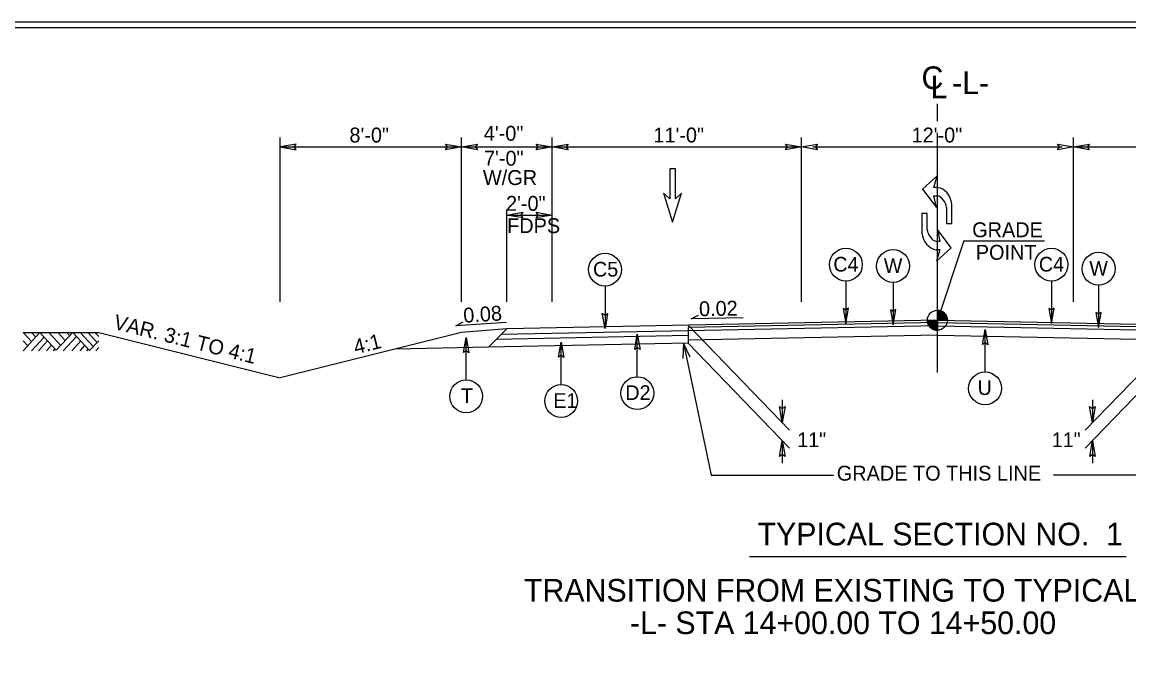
# Model space of a CAD drawing. Extents: x 1901718 to 1902220, y 193828 to 194187.
# Drawn here: x 1902010.31 to 1902059.14, y 194017.77 to 194045.77 of the extents above; entities that cross this region are included whole.
import ezdxf

# ---------------------------------------------------------------- set-up
doc = ezdxf.new("R2010")
doc.units = 0
for name, color, linetype in [('MARK BIKE LEFT ARROW CELL', 7, 'Continuous'), ('Old_Level_1', 7, 'Continuous'), ('Old_Level_11', 7, 'Continuous'), ('Old_Level_2', 7, 'Continuous'), ('Old_Level_20', 7, 'Continuous'), ('Old_Level_3', 7, 'Continuous'), ('Prop Dimension', 7, 'Continuous'), ('Prop Dimension Text', 7, 'Continuous'), ('Sheet Border Standard 30in CELL', 7, 'Continuous'), ('Sheet Plot Border Inside CELL', 7, 'Continuous'), ('Typical Terminator CELL', 7, 'Continuous')]:
    doc.layers.add(name, color=color, linetype=linetype)

# ---------------------------------------------------------------- blocks, each defined once
blk = doc.blocks.new('TERMINATOR')
at = {"layer": 'Typical Terminator CELL'}
blk.add_lwpolyline([(-0.469, 0.081), (0, 0), (-0.471, -0.083), (-0.411, 0)], close=True, dxfattribs=at)

msp = doc.modelspace()

# ---------------------------------------------------------------- linework, layer by layer
at = {"layer": 'MARK BIKE LEFT ARROW CELL'}
for p, q in [((1902050.682, 194038.984), (1902050.031, 194038.399)), ((1902050.682, 194038.984), (1902050.031, 194038.399)), ((1902050.531, 194038.476), (1902050.682, 194038.984)), ((1902050.531, 194038.476), (1902050.682, 194038.984)), ((1902050.031, 194038.399), (1902050.647, 194037.591)), ((1902050.031, 194038.399), (1902050.647, 194037.591)), ((1902050.705, 194038.476), (1902050.531, 194038.476)), ((1902050.705, 194038.476), (1902050.531, 194038.476)), ((1902050.531, 194038.11), (1902050.685, 194038.111)), ((1902050.531, 194038.11), (1902050.685, 194038.111)), ((1902050.647, 194037.591), (1902050.531, 194038.11)), ((1902050.647, 194037.591), (1902050.531, 194038.11)), ((1902051.096, 194037.591), (1902051.096, 194036.885)), ((1902051.096, 194037.591), (1902051.096, 194036.885)), ((1902051.327, 194036.885), (1902051.327, 194037.745)), ((1902051.327, 194036.885), (1902051.327, 194037.745)), ((1902050.241, 194037.323), (1902050.01, 194037.323)), ((1902050.01, 194037.323), (1902050.01, 194036.463)), ((1902050.241, 194037.323), (1902050.01, 194037.323)), ((1902050.01, 194037.323), (1902050.01, 194036.463)), ((1902050.241, 194036.617), (1902050.241, 194037.323)), ((1902050.241, 194036.617), (1902050.241, 194037.323)), ((1902051.096, 194036.885), (1902051.327, 194036.885)), ((1902051.096, 194036.885), (1902051.327, 194036.885)), ((1902051.306, 194035.808), (1902050.69, 194036.617)), ((1902050.69, 194036.617), (1902050.806, 194036.097)), ((1902051.306, 194035.808), (1902050.69, 194036.617)), ((1902050.69, 194036.617), (1902050.806, 194036.097)), ((1902050.806, 194036.097), (1902050.652, 194036.097)), ((1902050.806, 194036.097), (1902050.652, 194036.097)), ((1902050.633, 194035.732), (1902050.806, 194035.732)), ((1902050.633, 194035.732), (1902050.806, 194035.732)), ((1902050.655, 194035.223), (1902051.306, 194035.808)), ((1902050.655, 194035.223), (1902051.306, 194035.808)), ((1902050.806, 194035.732), (1902050.655, 194035.223)), ((1902050.806, 194035.732), (1902050.655, 194035.223))]:
    msp.add_line(p, q, dxfattribs=at)
for centre, major_axis, ratio in [((1902050.769, 194037.809), (-0.294, 0.632), 0.75825), ((1902050.769, 194037.809), (-0.294, 0.632), 0.75825), ((1902050.75, 194037.656), (-0.204, 0.44), 0.652763), ((1902050.75, 194037.656), (-0.204, 0.44), 0.652763), ((1902050.568, 194036.398), (0.294, -0.632), 0.75825), ((1902050.568, 194036.398), (0.294, -0.632), 0.75825), ((1902050.587, 194036.552), (0.204, -0.44), 0.652763), ((1902050.587, 194036.552), (0.204, -0.44), 0.652763)]:
    msp.add_ellipse(centre, major_axis=major_axis, ratio=ratio, start_param=4.277405, end_param=5.848201, dxfattribs=at)
at = {"layer": 'Old_Level_1'}
for p, q in [((1902050.692, 194041.404), (1902050.692, 194042.172)), ((1902050.692, 194030.313), (1902050.692, 194040.884)), ((1902050.692, 194032.619), (1902050.692, 194033.06)), ((1902029.445, 194032.369), (1902029.77, 194032.55)), ((1902031.68, 194032.515), (1902029.445, 194032.369)), ((1902050.692, 194032.619), (1902031.692, 194032.239)), ((1902050.692, 194032.515), (1902039.692, 194032.295)), ((1902039.825, 194032.674), (1902040.158, 194032.841)), ((1902042.129, 194032.722), (1902039.825, 194032.674)), ((1902050.251, 194032.619), (1902050.692, 194032.619)), ((1902050.691, 194032.178), (1902050.692, 194032.619)), ((1902050.692, 194032.619), (1902050.691, 194032.178)), ((1902050.692, 194032.619), (1902069.692, 194032.239)), ((1902051.133, 194032.619), (1902050.692, 194032.619)), ((1902050.692, 194032.515), (1902061.692, 194032.295)), ((1902010.35, 194032.079), (1902010.725, 194031.676)), ((1902010.35, 194031.274), (1902011.092, 194032.071)), ((1902010.725, 194032.079), (1902010.912, 194031.878)), ((1902011.092, 194032.071), (1902011.816, 194031.292)), ((1902011.483, 194032.079), (1902012.016, 194031.506)), ((1902011.816, 194031.292), (1902012.547, 194032.078)), ((1902011.881, 194032.079), (1902012.214, 194031.72)), ((1902012.283, 194032.079), (1902012.416, 194031.936)), ((1902012.547, 194032.078), (1902013.288, 194031.282)), ((1902012.869, 194032.079), (1902013.449, 194031.456)), ((1902013.202, 194032.079), (1902013.616, 194031.635)), ((1902013.522, 194032.079), (1902013.692, 194031.896)), ((1902013.692, 194032.079), (1902021.692, 194030.079)), ((1902029.692, 194032.079), (1902021.692, 194030.079)), ((1902031.692, 194032.239), (1902029.692, 194032.079)), ((1902031.692, 194032.239), (1902030.885, 194031.431)), ((1902039.692, 194032.149), (1902031.437, 194031.984)), ((1902039.692, 194032.399), (1902044.169, 194027.774)), ((1902050.692, 194032.369), (1902039.692, 194032.149)), ((1902039.692, 194032.295), (1902039.692, 194031.607)), ((1902050.692, 194032.369), (1902061.692, 194032.149)), ((1902061.692, 194032.399), (1902057.216, 194027.774)), ((1902010.35, 194031.717), (1902010.556, 194031.495)), ((1902010.724, 194031.274), (1902011.278, 194031.87)), ((1902011.033, 194031.274), (1902011.434, 194031.703)), ((1902011.38, 194031.274), (1902011.607, 194031.517)), ((1902012.126, 194031.274), (1902012.712, 194031.902)), ((1902012.496, 194031.274), (1902012.896, 194031.703)), ((1902012.862, 194031.274), (1902013.079, 194031.507)), ((1902013.288, 194031.282), (1902013.692, 194031.717)), ((1902039.692, 194031.607), (1902030.885, 194031.431)), ((1902039.692, 194031.94), (1902031.225, 194031.771)), ((1902050.692, 194031.953), (1902039.692, 194031.733)), ((1902039.692, 194031.607), (1902044.169, 194026.982)), ((1902050.692, 194031.953), (1902061.692, 194031.733)), ((1902061.692, 194031.607), (1902057.216, 194026.982)), ((1902011.691, 194031.274), (1902011.762, 194031.35)), ((1902013.157, 194031.274), (1902013.226, 194031.348)), ((1902013.558, 194031.274), (1902013.692, 194031.417)), ((1902030.885, 194031.431), (1902026.772, 194031.348)), ((1902043.85, 194029.103), (1902043.85, 194028.103)), ((1902057.535, 194029.103), (1902057.535, 194028.103)), ((1902043.85, 194027.312), (1902043.85, 194026.312)), ((1902057.535, 194027.312), (1902057.535, 194026.312))]:
    msp.add_line(p, q, dxfattribs=at)
for points in [[(1902050.696, 194033.06), (1902050.696, 194033.06), (1902050.696, 194032.619)], [(1902050.705, 194033.06), (1902050.705, 194032.619)], [(1902050.714, 194033.059), (1902050.714, 194032.619)], [(1902050.723, 194033.059), (1902050.723, 194032.619)], [(1902050.732, 194033.058), (1902050.732, 194032.619)], [(1902050.74, 194033.057), (1902050.74, 194032.619)], [(1902050.749, 194033.056), (1902050.749, 194032.619)], [(1902050.758, 194033.055), (1902050.758, 194032.619)], [(1902050.767, 194033.054), (1902050.767, 194032.619)], [(1902050.776, 194033.052), (1902050.776, 194032.619)], [(1902050.785, 194033.05), (1902050.785, 194032.619)], [(1902050.793, 194033.048), (1902050.793, 194032.619)], [(1902050.802, 194033.046), (1902050.802, 194032.619)], [(1902050.811, 194033.043), (1902050.811, 194032.619)], [(1902050.82, 194033.041), (1902050.82, 194032.619)], [(1902050.829, 194033.038), (1902050.829, 194032.619)], [(1902050.837, 194033.035), (1902050.837, 194032.619)], [(1902050.846, 194033.032), (1902050.846, 194032.619)], [(1902050.855, 194033.028), (1902050.855, 194032.619)], [(1902050.864, 194033.024), (1902050.864, 194032.619)], [(1902050.873, 194033.02), (1902050.873, 194032.619)], [(1902050.882, 194033.017), (1902050.882, 194032.619)], [(1902050.89, 194033.013), (1902050.89, 194032.619)], [(1902050.899, 194033.008), (1902050.899, 194032.619)], [(1902050.908, 194033.003), (1902050.908, 194032.619)], [(1902050.917, 194032.998), (1902050.917, 194032.619)], [(1902050.926, 194032.993), (1902050.926, 194032.619)], [(1902050.934, 194032.987), (1902050.934, 194032.619)], [(1902050.943, 194032.981), (1902050.943, 194032.619)], [(1902050.952, 194032.974), (1902050.952, 194032.619)], [(1902050.253, 194032.619), (1902050.253, 194032.571)], [(1902050.262, 194032.619), (1902050.262, 194032.519)], [(1902050.271, 194032.619), (1902050.271, 194032.487)], [(1902050.28, 194032.619), (1902050.28, 194032.461)], [(1902050.289, 194032.619), (1902050.289, 194032.44)], [(1902050.297, 194032.619), (1902050.297, 194032.422)], [(1902050.306, 194032.619), (1902050.306, 194032.405)], [(1902050.315, 194032.619), (1902050.315, 194032.389)], [(1902050.324, 194032.619), (1902050.324, 194032.376)], [(1902050.333, 194032.619), (1902050.333, 194032.363)], [(1902050.342, 194032.619), (1902050.342, 194032.351)], [(1902050.35, 194032.619), (1902050.35, 194032.34)], [(1902050.359, 194032.619), (1902050.359, 194032.33)], [(1902050.368, 194032.619), (1902050.368, 194032.32)], [(1902050.377, 194032.619), (1902050.377, 194032.31)], [(1902050.386, 194032.619), (1902050.386, 194032.301)], [(1902050.395, 194032.619), (1902050.395, 194032.293)], [(1902050.403, 194032.619), (1902050.403, 194032.285)], [(1902050.412, 194032.619), (1902050.412, 194032.278)], [(1902050.421, 194032.619), (1902050.421, 194032.271)], [(1902050.43, 194032.619), (1902050.43, 194032.264)], [(1902050.439, 194032.619), (1902050.439, 194032.258)], [(1902050.447, 194032.619), (1902050.447, 194032.252)], [(1902050.456, 194032.619), (1902050.456, 194032.246)], [(1902050.465, 194032.619), (1902050.465, 194032.24)], [(1902050.474, 194032.619), (1902050.474, 194032.235)], [(1902050.483, 194032.619), (1902050.483, 194032.231)], [(1902050.492, 194032.619), (1902050.492, 194032.226)], [(1902050.5, 194032.619), (1902050.5, 194032.222)], [(1902050.509, 194032.619), (1902050.509, 194032.218)], [(1902050.518, 194032.619), (1902050.518, 194032.214)], [(1902050.527, 194032.619), (1902050.527, 194032.21)], [(1902050.536, 194032.619), (1902050.536, 194032.206)], [(1902050.544, 194032.619), (1902050.544, 194032.203)], [(1902050.553, 194032.619), (1902050.553, 194032.2)], [(1902050.562, 194032.619), (1902050.562, 194032.197)], [(1902050.571, 194032.619), (1902050.571, 194032.195)], [(1902050.58, 194032.619), (1902050.58, 194032.192)], [(1902050.589, 194032.619), (1902050.589, 194032.19)], [(1902050.597, 194032.619), (1902050.597, 194032.188)], [(1902050.606, 194032.619), (1902050.606, 194032.186)], [(1902050.615, 194032.619), (1902050.615, 194032.185)], [(1902050.624, 194032.619), (1902050.624, 194032.184)], [(1902050.633, 194032.619), (1902050.633, 194032.182)], [(1902050.641, 194032.619), (1902050.641, 194032.181)], [(1902050.65, 194032.619), (1902050.65, 194032.18)], [(1902050.659, 194032.619), (1902050.659, 194032.179)], [(1902050.668, 194032.619), (1902050.668, 194032.179)], [(1902050.677, 194032.619), (1902050.677, 194032.178)], [(1902050.686, 194032.619), (1902050.686, 194032.178), (1902050.686, 194032.178)], [(1902050.961, 194032.969), (1902050.961, 194032.619)], [(1902050.97, 194032.962), (1902050.97, 194032.619)], [(1902050.979, 194032.954), (1902050.979, 194032.619)], [(1902050.987, 194032.946), (1902050.987, 194032.619)], [(1902050.996, 194032.938), (1902050.996, 194032.619)], [(1902051.005, 194032.929), (1902051.005, 194032.619)], [(1902051.014, 194032.921), (1902051.014, 194032.619)], [(1902051.023, 194032.911), (1902051.023, 194032.619)], [(1902051.032, 194032.9), (1902051.032, 194032.619)], [(1902051.04, 194032.889), (1902051.04, 194032.619)], [(1902051.049, 194032.877), (1902051.049, 194032.619)], [(1902051.058, 194032.865), (1902051.058, 194032.619)], [(1902051.067, 194032.851), (1902051.067, 194032.619)], [(1902051.076, 194032.836), (1902051.076, 194032.619)], [(1902051.084, 194032.821), (1902051.084, 194032.619)], [(1902051.093, 194032.802), (1902051.093, 194032.619)], [(1902051.102, 194032.781), (1902051.102, 194032.619)], [(1902051.111, 194032.757), (1902051.111, 194032.619)], [(1902051.12, 194032.726), (1902051.12, 194032.619)], [(1902051.129, 194032.681), (1902051.129, 194032.619)], [(1902010.35, 194032.079), (1902013.692, 194032.079)], [(1902039.788, 194030.994), (1902039.495, 194031.603), (1902039.467, 194030.927)], [(1902039.495, 194031.603), (1902040.711, 194025.788), (1902046.102, 194025.788)], [(1902062.414, 194031.592), (1902061.2, 194025.788), (1902055.809, 194025.788)]]:
    msp.add_lwpolyline(points, dxfattribs=at)
msp.add_circle((1902050.692, 194032.619), 0.441, dxfattribs=at)
for start, end in [(359.9905, 89.9905), (179.9905, 269.9905)]:
    msp.add_arc((1902050.692, 194032.619), 0.441, start, end, dxfattribs=at)
at = {"layer": 'Old_Level_11'}
for p, q in [((1902036.027, 194034.125), (1902036.027, 194032.251)), ((1902046.654, 194034.346), (1902046.654, 194032.472)), ((1902048.737, 194034.286), (1902048.737, 194032.412)), ((1902055.723, 194034.346), (1902055.723, 194032.472)), ((1902057.805, 194034.166), (1902057.805, 194032.292)), ((1902037.451, 194030.129), (1902037.451, 194032.003)), ((1902052.796, 194030.338), (1902052.796, 194032.212)), ((1902029.9, 194029.987), (1902029.9, 194031.862)), ((1902034.092, 194029.781), (1902034.092, 194031.655)), ((1902042.4, 194022.191), (1902059.026, 194022.191))]:
    msp.add_line(p, q, dxfattribs=at)
for points in [[(1902046.539, 194033.143), (1902046.654, 194032.472), (1902046.774, 194033.147), (1902046.654, 194033.061)], [(1902048.621, 194033.083), (1902048.737, 194032.412), (1902048.856, 194033.087), (1902048.737, 194033.001)], [(1902055.607, 194033.143), (1902055.723, 194032.472), (1902055.842, 194033.147), (1902055.723, 194033.061)], [(1902036.142, 194032.922), (1902036.027, 194032.251), (1902035.907, 194032.926), (1902036.027, 194032.84)], [(1902057.689, 194032.963), (1902057.805, 194032.292), (1902057.924, 194032.967), (1902057.805, 194032.881)], [(1902037.336, 194031.332), (1902037.451, 194032.003), (1902037.571, 194031.328), (1902037.451, 194031.414)], [(1902052.68, 194031.541), (1902052.796, 194032.212), (1902052.915, 194031.537), (1902052.796, 194031.623)], [(1902029.784, 194031.19), (1902029.9, 194031.862), (1902030.019, 194031.186), (1902029.9, 194031.272)], [(1902033.977, 194030.983), (1902034.092, 194031.655), (1902034.212, 194030.98), (1902034.092, 194031.065)]]:
    msp.add_lwpolyline(points, close=True, dxfattribs=at)
for centre in [(1902036.027, 194034.85), (1902046.655, 194035.071), (1902048.737, 194035.011), (1902055.723, 194035.071), (1902057.805, 194034.891), (1902037.452, 194029.404), (1902052.796, 194029.613), (1902029.9, 194029.262), (1902034.092, 194029.055)]:
    msp.add_circle(centre, 0.725, dxfattribs=at)
at = {"layer": 'Old_Level_3'}
for q in [(1902050.692, 194032.619), (1902055.419, 194036.123)]:
    msp.add_line((1902051.855, 194036.123), q, dxfattribs=at)
at = {"layer": 'Prop Dimension'}
for p, q in [((1902021.692, 194033.43), (1902021.692, 194040.682)), ((1902029.692, 194033.43), (1902029.692, 194040.682)), ((1902033.692, 194033.43), (1902033.692, 194040.682)), ((1902044.692, 194033.43), (1902044.692, 194040.682)), ((1902056.692, 194033.43), (1902056.692, 194040.682)), ((1902033.692, 194040.263), (1902044.692, 194040.263)), ((1902045.192, 194040.263), (1902056.192, 194040.263)), ((1902056.692, 194040.263), (1902067.692, 194040.263)), ((1902031.692, 194033.43), (1902031.692, 194037.509)), ((1902031.692, 194037.259), (1902033.692, 194037.259))]:
    msp.add_line(p, q, dxfattribs=at)
msp.add_lwpolyline([(1902039.405, 194038.218), (1902039.134, 194037.968), (1902039.134, 194039.302), (1902038.884, 194039.302), (1902038.884, 194037.968), (1902038.614, 194038.218), (1902039.009, 194036.948)], close=True, dxfattribs=at)
msp.add_lwpolyline([(1902039.405, 194038.218), (1902039.134, 194037.968), (1902039.134, 194039.302), (1902038.884, 194039.302), (1902038.884, 194037.968), (1902038.614, 194038.218), (1902039.009, 194036.948)], close=True, dxfattribs=at)
at = {"layer": 'Prop Dimension Text'}
for p, q in [((1902021.692, 194040.263), (1902029.692, 194040.263)), ((1902029.692, 194040.263), (1902033.692, 194040.263))]:
    msp.add_line(p, q, dxfattribs=at)
at = {"layer": 'Sheet Border Standard 30in CELL'}
msp.add_lwpolyline([(1902132.544, 194045.514), (1901982.544, 194045.514), (1901982.544, 193940.514), (1902132.544, 193940.514)], close=True, dxfattribs=at)
at = {"layer": 'Sheet Plot Border Inside CELL'}
msp.add_lwpolyline([(1902133.794, 194045.769), (1901967.144, 194045.769), (1901967.144, 193940.259), (1902133.794, 193940.259)], close=True, dxfattribs=at)

# ---------------------------------------------------------------- block references
at = {"layer": 'Old_Level_1', "xscale": 1.5, "yscale": 1.5}
for p, rotation in [((1902043.85, 194028.103), -90), ((1902057.535, 194028.103), -90), ((1902043.85, 194027.312), 90), ((1902057.535, 194027.312), 90)]:
    msp.add_blockref('TERMINATOR', p, dxfattribs=dict(at, rotation=rotation))
at = {"layer": 'Prop Dimension', "xscale": 1.5, "rotation": 180}
for p, yscale in [((1902021.692, 194040.263), -1.5), ((1902029.692, 194040.263), 1.5), ((1902033.692, 194040.263), 1.5), ((1902044.692, 194040.263), 1.5), ((1902056.692, 194040.263), 1.5), ((1902031.692, 194037.259), 1.5)]:
    msp.add_blockref('TERMINATOR', p, dxfattribs=dict(at, yscale=yscale))
at = {"layer": 'Prop Dimension', "xscale": 1.5, "yscale": 1.5}
for p in [(1902029.692, 194040.263), (1902033.692, 194040.263), (1902044.692, 194040.263), (1902056.692, 194040.263), (1902033.692, 194037.259)]:
    msp.add_blockref('TERMINATOR', p, dxfattribs=at)

# ---------------------------------------------------------------- texts
at = {"layer": 'Old_Level_1'}
for s, rotation, p in [('VAR. 3:1 TO 4:1', 345.9638, (1902014.301, 194032.246)), ('4:1', 14.0362, (1902025.025, 194031.109))]:
    msp.add_text(s, height=0.656, rotation=rotation, dxfattribs=at).set_placement(p)
for s, height, p in [('11"', 0.6491, (1902044.509, 194027.02)), ('11"', 0.6491, (1902055.74, 194027.02)), ('GRADE TO THIS LINE', 0.656, (1902046.253, 194025.542))]:
    msp.add_text(s, height=height, dxfattribs=at).set_placement(p)
at = {"layer": 'Old_Level_11'}
for s, p in [('TYPICAL SECTION NO.  1', (1902042.756, 194022.685)), ('TRANSITION FROM EXISTING TO TYPICAL SECTION NO. 1', (1902032.45, 194020.204)), ('-L- STA 14+00.00 TO 14+50.00', (1902037.126, 194018.771))]:
    msp.add_text(s, height=1, dxfattribs=at).set_placement(p)
at = {"layer": 'Old_Level_2'}
msp.add_text('C', height=1, dxfattribs=at).set_placement((1902049.991, 194042.817))
for s, height, rotation, p in [('L', 1, 359.9469, (1902050.393, 194042.413)), ('-L-', 1, 359.9469, (1902051.341, 194042.596)), ('0.02', 0.656, 1.1916, (1902040.181, 194032.793)), ('0.08', 0.656, 3.7166, (1902029.795, 194032.503))]:
    msp.add_text(s, height=height, rotation=rotation, dxfattribs=at).set_placement(p)
at = {"layer": 'Old_Level_20'}
for s, height, p in [('C4', 0.6491, (1902046.101, 194034.765)), ('C4', 0.6491, (1902055.169, 194034.765)), ('C5', 0.6491, (1902035.498, 194034.544)), ('W', 0.649, (1902048.328, 194034.705)), ('W', 0.649, (1902057.396, 194034.585)), ('T', 0.649, (1902029.672, 194028.969)), ('D2', 0.6491, (1902036.925, 194029.1)), ('U', 0.649, (1902052.468, 194029.32)), ('E1', 0.6491, (1902033.747, 194028.752))]:
    msp.add_text(s, height=height, dxfattribs=at).set_placement(p)
at = {"layer": 'Old_Level_3'}
for s, p in [('GRADE', (1902052.228, 194036.281)), ('POINT', (1902052.386, 194035.287))]:
    msp.add_text(s, height=0.656, dxfattribs=at).set_placement(p)
at = {"layer": 'Prop Dimension'}
for s, p in [('11\'-0" ', (1902038.162, 194040.461)), ('12\'-0" ', (1902049.555, 194040.461))]:
    msp.add_text(s, height=0.656, dxfattribs=at).set_placement(p)
for s, p in [('2\'-0"', (1902031.66, 194037.447)), ('FDPS', (1902031.708, 194036.463))]:
    msp.add_text(s, height=0.656, rotation=360, dxfattribs=at).set_placement(p)
at = {"layer": 'Prop Dimension Text'}
for s, p in [('8\'-0"', (1902024.75, 194040.461)), ('4\'-0"', (1902030.679, 194040.538)), ('7\'-0"', (1902030.688, 194039.437)), ('W/GR', (1902030.641, 194038.584))]:
    msp.add_text(s, height=0.656, dxfattribs=at).set_placement(p)

doc.saveas('drawing.dxf')
